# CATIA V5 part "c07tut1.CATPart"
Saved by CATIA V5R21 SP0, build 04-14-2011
Part number: Part1
Bounding box of the stored display mesh (mm): x -150 to 150, y -150 to 150, z -127.513 to 0
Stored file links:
  D:\CATIA V5R21 E-RESOURCES\CATIA-V5R21\catia-v5r21-prt\c07-catia-v5r20-prt\c07-catia-v5r21-tut01.CATPart
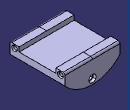
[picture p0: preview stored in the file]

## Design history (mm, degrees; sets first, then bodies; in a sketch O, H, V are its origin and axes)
Body1 (main body)
  Sketch1 on zx-plane, origin (0, 0, 0), H (-1, 0, 0), V (0, 0, 1)
    line L1 (0, 0) -> (150, 0)
    point P1 (150, 0)
    line L2 (150, 0) -> (150, -60)
    point P2 (150, -60)
    point P3 (-150, -60)
    point P4 (-150, 0)
    line L3 (-150, 0) -> (-150, -60)
    point P5 (0, 0)
    line L4 (0, 0) -> (-150, 0)
    arc A1 centre (0, 72.2876) radius 200 from (-150, -60) to (150, -60) ccw
    point P6 (0, 72.2876)
    distance L3 L2 = 300
    length L2 = 60
    radius A1 = 200
    horizontal: L1 H
    vertical: L2 V
    symmetry: P2 P3 V, P1 P4 V, L2 L3 V, O P5 V, L1 L4 V
    coincidence: P6 V, O P5
  Pad1: profile Sketch1, direction (0, 1, 0), length 150, mirrored extent
  Sketch2 on face of Pad1 from Sketch1.L3, origin (150, 0, 0), H (0, 1, 0), V (0, 0, 1)
    line L1 (-100, 0) -> (100, 0)
    reference projected line E1 (-150, 0) -> (150, 0) from edge [face of Pad1 from Sketch1.L3 | face of Pad1 from Sketch1.L4]
    line L2 (-100, 0) -> (-100, -25)
    line L3 (-100, -25) -> (100, -25)
    line L4 (100, 0) -> (100, -25)
    length L1 = 200
    distance L3 L1 = 25
    distance L4 V = 100
    coincidence: E1 L1
    vertical: L2 V, L4 V
    horizontal: L3 H
  Pocket1: profile Sketch2, direction (-1, 0, 0), through (limit type 3)
  Sketch3 on face of Pad1 from Sketch1.L3, origin (150, 95.7656, -28.4411), H (0, 1, 0), V (0, 0, 1)
    point P1 (29.2344, 8.4411)
    reference projected line E1 (-245.7656, 28.4411) -> (54.2344, 28.4411) from edge [face of Pad1 from Sketch1.L3 | face of Pad1 from Sketch1.L4]
    reference projected line E2 (54.2344, 28.4411) -> (54.2344, -31.5589) from edge [face of Pad1 from Sketch1.L3 | end face of Pad1]
    distance P1 E1 = 20
    distance P1 E2 = 25
  Hole1: placed by Sketch3, at (150, 125, -20) direction (-1, 0, 0), diameter 20, through (limit type 3), countersink depth 5, countersink angle 90
  Sketch4 on face of Pad1 from Sketch1.L3, origin (150, -127.9074, -34.2074), H (0, 1, 0), V (0, 0, 1)
    point P1 (2.9074, 14.2074)
    reference projected line E1 (-22.0926, 34.2074) -> (-22.0926, -25.7926) from edge [start face of Pad1 | face of Pad1 from Sketch1.L3]
    reference projected line E2 (-22.0926, 34.2074) -> (277.9074, 34.2074) from edge [face of Pad1 from Sketch1.L3 | face of Pad1 from Sketch1.L4]
    distance P1 E1 = 25
    distance P1 E2 = 20
  Hole2: placed by Sketch4, at (150, -125, -20) direction (-1, 0, 0), diameter 20, through (limit type 3), countersink depth 5, countersink angle 90
  Sketch5 on end face of Pad1, origin (-54.7231, 150, -53.7681), H (1, 0, 0), V (0, 0, -1)
    point P1 (54.7231, 46.2319)
    reference projected line E1 (54.7231, -53.7681) -> (204.7231, -53.7681) from edge [face of Pad1 from Sketch1.L4 | end face of Pad1]
    reference projected line E2 (-95.2769, 6.2319) -> (-95.2769, -53.7681) from edge [face of Pad1 from Sketch1.L2 | end face of Pad1]
    distance E1 P1 = 100
    distance E2 P1 = 150
  Hole3: placed by Sketch5, at (0, 150, -100) direction (0, -1, 0), diameter 30, through (limit type 3), counterbore diameter 40, counterbore depth 15
  Fillet1: radius 10, on edge [face of Pad1 from Sketch1.L1 | end face of Pad1]; edge [start face of Pad1 | face of Pad1 from Sketch1.L1]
